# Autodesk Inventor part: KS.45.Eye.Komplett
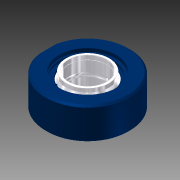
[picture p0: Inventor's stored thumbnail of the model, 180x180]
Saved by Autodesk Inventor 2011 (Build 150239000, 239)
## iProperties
Created: 2010-10
Part Number: KS.45.Eye.Komplett
Document SubType Name: Modeling
Designer: tribel
Density: 1 g/cm^3
Author: tribel
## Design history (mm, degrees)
derived "KS.45.eye.iam"
body "Solid1"
node "Part18.ipt:1"
node "Part24.ipt:1"
node "Part32.ipt:1"
node "Part34.ipt:1"
sketch "Part36.ipt:1"
node "Part40.ipt:1"
